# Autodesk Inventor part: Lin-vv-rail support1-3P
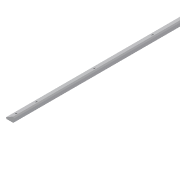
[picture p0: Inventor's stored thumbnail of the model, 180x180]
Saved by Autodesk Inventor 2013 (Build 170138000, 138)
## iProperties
Created: 2012-05
Part Number: Lin-vv-rail support1-3P
Document SubType Name: Modeling
Designer: ssc
Density: 7.9 g/cm^3
Material: Stainless Steel, 304
Mass: 35916 g
Surface Area: 8775.68 cm^2
Volume: 4546.33 cm^3
Description: RAIL SUPPORT
Author: ssc
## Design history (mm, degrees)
sketch "Sketch1" dims "d9" = 350.012
  geometry: L1 (-171.45, 398.323)-(171.45, 398.323); L2 (171.45, 398.323)-(171.45, 416.103); L3 (171.45, 416.103)-(-171.45, 416.103); L4 (-171.45, 416.103)-(-171.45, 398.323); L5 (0, 0)-(0, 522.288); L6 (-227.13, 378.663)-(52.27, 378.663); L7 (-166.688, 93.663)-(-166.688, -53.314); L8 (-249.551, 385.46)-(-182.876, 385.46); L9 (-182.876, 385.46)-(-182.876, 375.935); L10 (-182.876, 375.935)-(-249.551, 375.935); L11 (-249.551, 375.935)-(-249.551, 385.46); L12 (-205.101, 385.46)-(-189.226, 385.46); L13 (-189.226, 385.46)-(-189.226, 382.92); L14 (-189.226, 382.92)-(-205.101, 382.92); L15 (-205.101, 382.92)-(-205.101, 385.46); L16 (-220.099, 394.985)-(-249.551, 394.985); L17 (-252.484, 400.065)-(-220.224, 418.69); L18 (-216.924, 412.975)-(-216.924, 398.16); L19 (-220.224, 418.69)-(-216.924, 412.975); L20 (-252.484, 400.065)-(-249.551, 394.985); L21 (-195.631, 418.086)-(-184.633, 418.086); L22 (-184.633, 418.086)-(-184.633, 398.096); L23 (-184.633, 398.096)-(-195.631, 398.096); L24 (-195.631, 398.096)-(-195.631, 418.086); L25 (-220.099, 394.985)-(-216.924, 398.16); A1 r 473.075 centre (0, 0) between (-252.484, 400.065) and (-220.224, 418.69); 4 further points
  constraints: 50 end point, 9 parallel, 8 point on line, 6 perpendicular, 5 horizontal, 2 point on circle, 1 centre point, 1 coincident, 4 other
  dimensions: "d0" = 946.15 diameter of A1; "d1" = 398.3228 distance from line of L5.start L1; "d2" = 17.78 distance of L1.end L2.end; "d3" = 342.9 distance of L2.end L3.end; "d4" = 171.45 distance between parallel lines of L2 L5; "d5" = 19.6596 distance between parallel lines of L6 L1; "d10" = 9.525 distance of L8.end L9.end; "d11" = 66.675 distance of L9.end L10.end; "d13" = 15.875 distance of L13.end L14.end; "d14" = 6.35 distance between parallel lines of L9 L13; "d15" = 2.54 distance between parallel lines of L14 L8; "d23" = 60 deg angle of L18 L17; "d24" = 3.81 distance of L17.end point (-216.924, 420.595); "d25" = 90 deg angle of L17 L19; "d26" = 10.16 distance of L17.start point (-261.283, 394.985); "d27" = 90 deg angle of L17 L20 (= d25); "d29" = 35.56 distance from line of L18 L17.start; "d31" = 9.525 distance between parallel lines of L8 L16; "d47" = 216.92432 distance between parallel lines of L5 L18 (derived); "d48" = 10.9982 distance of L21.start L21.end; "d49" = 19.9898 distance of L23.end L21.start; "d50" = 184.6326 distance between parallel lines of L5 L22; "d51" = 3.175 distance of L16.start point (-216.924, 394.985); "d52" = 3.175 distance of L18.end point (-216.924, 394.985) (derived)
extrude "Extrusion1" new body sketch "Sketch1" distance "d32" = 8864.6; taper "d33" = 0 deg
hole "Hole1" diameter "d36" = 7.7978; stored, may be unused: countersink angle "d40" = 82 deg, drill point angle "d42" = 118 deg; dims "d34" = 15.875, "d35" = 114.3, "d37" = 12.7, "d38" = 9.525, "d39" = 6.35, "d41" = 12.7
hole "Hole2" diameter "d55" = 7.7978; stored, may be unused: countersink angle "d59" = 82 deg, drill point angle "d61" = 118 deg; dims "d53" = 25.4, "d54" = 15.875, "d56" = 12.7, "d57" = 9.525, "d58" = 6.35, "d60" = 19.05
hole "Hole3" diameter "d64" = 7.7978; stored, may be unused: countersink angle "d68" = 82 deg, drill point angle "d70" = 118 deg; dims "d62" = 25.4, "d63" = 15.875, "d65" = 12.7, "d66" = 9.525, "d67" = 6.35, "d69" = 19.05
body "Solid1"
pattern_linear "Rectangular Pattern1" dims "d45" = 254
